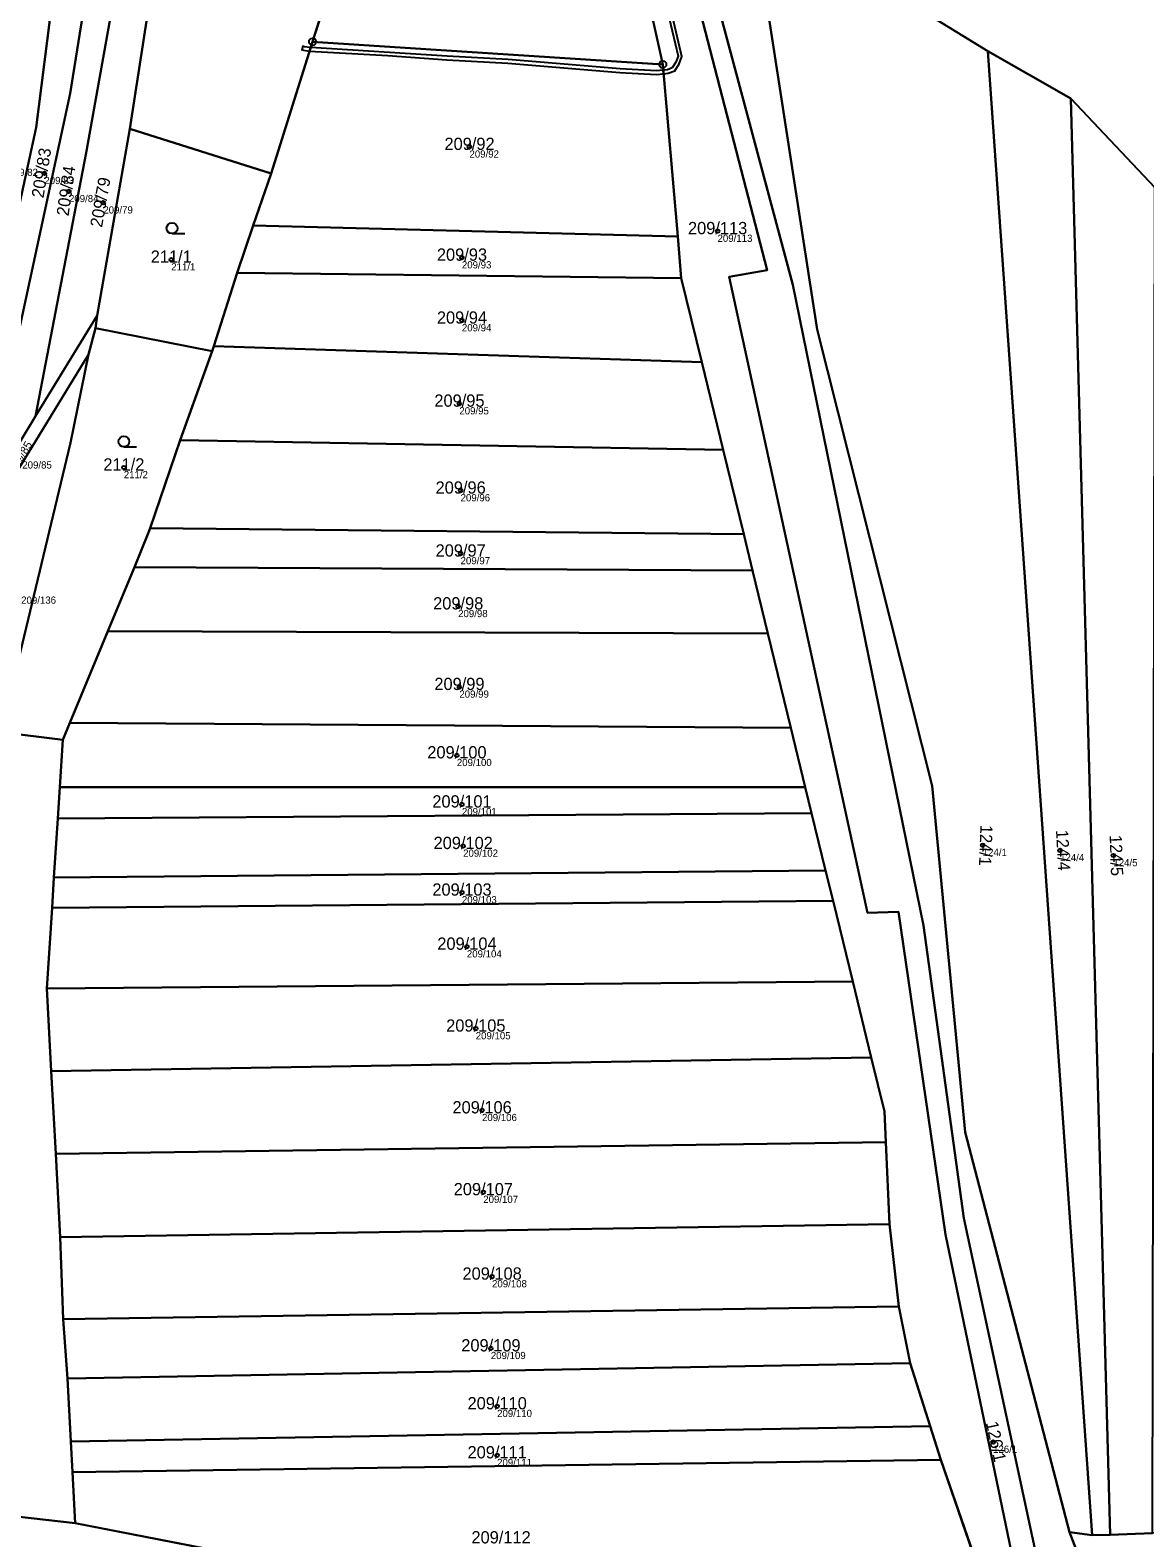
# Model space of a CAD drawing. Extents: x -603967 to -594699, y -1179315 to -1165625.
# Drawn here: x -597528.8 to -597374.2, y -1173008.8 to -1172799.8 of the extents above; entities that cross this region are included whole.
import ezdxf

# ---------------------------------------------------------------- set-up
doc = ezdxf.new("R2010")
doc.units = 0
for name, color, linetype in [('Definiční body', 7, 'Continuous'), ('Hranice parcel', 7, 'Continuous'), ('Parcelní čísla', 7, 'Continuous'), ('Polygon parcely', 7, 'Continuous'), ('Věcná břemena k části', 7, 'Continuous'), ('Značky bodu BP', 7, 'Continuous'), ('Značky kultur', 7, 'Continuous')]:
    doc.layers.add(name, color=color, linetype=linetype)

msp = doc.modelspace()

# ---------------------------------------------------------------- linework, layer by layer
at = {"layer": 'Definiční body'}
for centre in [(-597467.86, -1172815.98994), (-597526.79, -1172819.65994), (-597523.38, -1172822.15994), (-597518.62, -1172823.73994), (-597433.47, -1172827.66994), (-597468.91, -1172831.34994), (-597509.21, -1172831.62994), (-597468.91, -1172840.06994), (-597469.26, -1172851.58994), (-597515.78, -1172860.43994), (-597469.09, -1172863.63994), (-597469.09, -1172872.36994), (-597469.43, -1172879.69994), (-597469.26, -1172890.86994), (-597469.61, -1172900.34994), (-597468.91, -1172907.15994), (-597468.74, -1172912.91994), (-597396.7, -1172912.80994), (-597385.98, -1172913.52994), (-597378.59, -1172914.23994), (-597468.91, -1172919.37994), (-597468.22, -1172926.87994), (-597466.99, -1172938.22994), (-597466.12, -1172949.56994), (-597465.95, -1172960.91994), (-597464.73, -1172972.61994), (-597464.9, -1172982.56994), (-597464.03, -1172990.59994), (-597395.27, -1172995.56994), (-597464.03, -1172997.39994)]:
    msp.add_circle(centre, 0.25, dxfattribs=at)
at = {"layer": 'Hranice parcel'}
for p, q in [((-597440.1, -1172780.93), (-597426.6, -1172833.08)), ((-597484.17, -1172784.25), (-597489.6, -1172801.41)), ((-597445.39, -1172784.96), (-597441.07, -1172804.55)), ((-597395.98, -1172802.73), (-597418.94, -1172788.61)), ((-597489.6, -1172801.41), (-597495.37, -1172819.66)), ((-597441.07, -1172804.55), (-597489.6, -1172801.41)), ((-597384.49, -1172809.28), (-597395.98, -1172802.73)), ((-597381.55, -1173008.49), (-597395.98, -1172802.73)), ((-597438.99, -1172828.42), (-597441.07, -1172804.55)), ((-597379.03, -1173008.41), (-597384.49, -1172809.28)), ((-597372.84, -1172821.6), (-597384.49, -1172809.28)), ((-597519.47, -1172839.39), (-597514.93, -1172813.48)), ((-597514.93, -1172813.48), (-597495.37, -1172819.66)), ((-597495.37, -1172819.66), (-597497.83, -1172826.87)), ((-597497.83, -1172826.87), (-597500.07, -1172833.46)), ((-597497.83, -1172826.87), (-597438.99, -1172828.42)), ((-597438.49, -1172834.21), (-597438.99, -1172828.42)), ((-597500.07, -1172833.46), (-597503.32, -1172843.63)), ((-597500.07, -1172833.46), (-597438.49, -1172834.21)), ((-597435.65, -1172845.86), (-597438.49, -1172834.21)), ((-597528.03, -1172853.32), (-597519.47, -1172839.39)), ((-597519.7, -1172841.11), (-597519.47, -1172839.39)), ((-597520.68, -1172844.76), (-597519.7, -1172841.11)), ((-597503.54, -1172844.31), (-597519.7, -1172841.11)), ((-597503.32, -1172843.63), (-597503.54, -1172844.31)), ((-597503.32, -1172843.63), (-597435.65, -1172845.86)), ((-597530.61, -1172861.05), (-597520.68, -1172844.76)), ((-597503.54, -1172844.31), (-597507.98, -1172856.67)), ((-597432.7, -1172857.97), (-597435.65, -1172845.86)), ((-597536.07, -1172866.61), (-597528.03, -1172853.32)), ((-597507.98, -1172856.67), (-597512.13, -1172868.86)), ((-597507.98, -1172856.67), (-597432.7, -1172857.97)), ((-597429.84, -1172869.68), (-597432.7, -1172857.97)), ((-597512.13, -1172868.86), (-597429.84, -1172869.68)), ((-597428.61, -1172874.73), (-597429.84, -1172869.68)), ((-597514.32, -1172874.25), (-597518, -1172883.14)), ((-597514.32, -1172874.25), (-597428.61, -1172874.73)), ((-597426.48, -1172883.48), (-597428.61, -1172874.73)), ((-597518, -1172883.14), (-597523.27, -1172895.86)), ((-597518, -1172883.14), (-597426.48, -1172883.48)), ((-597423.3, -1172896.53), (-597426.48, -1172883.48)), ((-597523.27, -1172895.86), (-597524.24, -1172898.2)), ((-597523.27, -1172895.86), (-597423.3, -1172896.53)), ((-597524.24, -1172898.2), (-597532.79, -1172897.13)), ((-597524.24, -1172898.2), (-597524.66, -1172904.75)), ((-597421.3, -1172904.75), (-597423.3, -1172896.53)), ((-597524.66, -1172904.75), (-597524.94, -1172909.1)), ((-597524.66, -1172904.75), (-597421.3, -1172904.75)), ((-597420.42, -1172908.38), (-597421.3, -1172904.75)), ((-597524.94, -1172909.1), (-597420.42, -1172908.38)), ((-597418.48, -1172916.31), (-597420.42, -1172908.38)), ((-597524.94, -1172909.1), (-597525.46, -1172917.3)), ((-597525.46, -1172917.3), (-597418.48, -1172916.31)), ((-597417.46, -1172920.51), (-597418.48, -1172916.31)), ((-597525.46, -1172917.3), (-597525.73, -1172921.48)), ((-597525.73, -1172921.48), (-597417.46, -1172920.51)), ((-597414.73, -1172931.72), (-597417.46, -1172920.51)), ((-597525.73, -1172921.48), (-597526.44, -1172932.67)), ((-597526.44, -1172932.67), (-597414.73, -1172931.72)), ((-597526.44, -1172932.67), (-597525.83, -1172944.12)), ((-597412.16, -1172942.26), (-597414.73, -1172931.72)), ((-597525.83, -1172944.12), (-597412.16, -1172942.26)), ((-597525.83, -1172944.12), (-597525.22, -1172955.62)), ((-597525.22, -1172955.62), (-597410.15, -1172953.99)), ((-597409.65, -1172965.36), (-597410.15, -1172953.99)), ((-597525.22, -1172955.62), (-597524.61, -1172967.15)), ((-597524.61, -1172967.15), (-597409.65, -1172965.36)), ((-597524.61, -1172967.15), (-597524.21, -1172978.5)), ((-597408.34, -1172976.76), (-597409.65, -1172965.36)), ((-597524.21, -1172978.5), (-597408.34, -1172976.76)), ((-597406.76, -1172984.61), (-597408.34, -1172976.76)), ((-597524.21, -1172978.5), (-597523.57, -1172986.76)), ((-597523.57, -1172986.76), (-597406.76, -1172984.61)), ((-597403.99, -1172993.36), (-597406.76, -1172984.61)), ((-597523.57, -1172986.76), (-597523.11, -1172995.49)), ((-597523.11, -1172995.49), (-597403.99, -1172993.36)), ((-597402.51, -1172998.04), (-597403.99, -1172993.36)), ((-597523.11, -1172995.49), (-597522.89, -1172999.73)), ((-597522.89, -1172999.73), (-597402.51, -1172998.04)), ((-597396, -1173016.84), (-597402.51, -1172998.04)), ((-597522.89, -1172999.73), (-597522.51, -1173006.81)), ((-597522.51, -1173006.81), (-597435.74, -1173023.68)), ((-597384.66, -1173008.07), (-597366.96, -1173054.01)), ((-597384.66, -1173008.07), (-597381.55, -1173008.49)), ((-597381.55, -1173008.49), (-597379.03, -1173008.41)), ((-597379.03, -1173008.41), (-597373.16, -1173008.21))]:
    msp.add_line(p, q, dxfattribs=at)
for points in [[(-597537.99, -1172859.47), (-597527.91, -1172813.28), (-597523.41, -1172777.58)], [(-597534.46, -1172860.45), (-597523.22, -1172808.61), (-597518.36, -1172778.25)], [(-597514.19, -1172778.81), (-597520.99, -1172816.83), (-597528.03, -1172853.32)], [(-597514.93, -1172813.48), (-597511.25, -1172789.55), (-597509.62, -1172779.45)], [(-597341.88, -1173256.44), (-597340.26, -1173250.03), (-597339.32, -1173236.26), (-597344.17, -1173179.9), (-597353.54, -1173132.63), (-597361.17, -1173091.31), (-597366.08, -1173066.31), (-597374.64, -1173050.36), (-597380.37, -1173039.62), (-597387.47, -1173019.8), (-597399.32, -1172964.53), (-597404.92, -1172923.92), (-597423.04, -1172835.13), (-597437.05, -1172782.74)], [(-597424.67, -1172787.5), (-597427.53, -1172790.48), (-597419.68, -1172841.29), (-597403.71, -1172904.59), (-597399.15, -1172952.61), (-597384.66, -1173008.07)], [(-597426.6, -1172833.08), (-597431.85, -1172834.01), (-597412.69, -1172922.18), (-597408.39, -1172922.03), (-597401.86, -1172966.79), (-597391.47, -1173016.9), (-597386.2, -1173032.57)], [(-597532.79, -1172897.13), (-597523.17, -1172857.04), (-597520.68, -1172844.76)], [(-597512.13, -1172868.86), (-597512.34, -1172869.47), (-597514.32, -1172874.25)], [(-597410.15, -1172953.99), (-597410.34, -1172949.74), (-597412.16, -1172942.26)], [(-597522.51, -1173006.81), (-597530.67, -1173005.87), (-597534.65, -1173013.07)]]:
    msp.add_lwpolyline(points, dxfattribs=at)
at = {"layer": 'Polygon parcely'}
for points in [[(-597508.93, -1172775.18), (-597509.62, -1172779.45), (-597511.25, -1172789.55), (-597514.93, -1172813.48), (-597495.37, -1172819.66), (-597489.6, -1172801.41), (-597484.17, -1172784.25), (-597484.99, -1172777.4), (-597483.85, -1172750.31), (-597508.33, -1172749.24), (-597507.34, -1172765.31)], [(-597527.91, -1172813.28), (-597523.41, -1172777.58), (-597529.57, -1172776.75), (-597533.9, -1172807.29), (-597546.53, -1172872.69), (-597539.27, -1172859.11), (-597537.99, -1172859.47)], [(-597534.46, -1172860.45), (-597523.22, -1172808.61), (-597518.36, -1172778.25), (-597523.41, -1172777.58), (-597527.91, -1172813.28), (-597537.99, -1172859.47)], [(-597528.03, -1172853.32), (-597520.99, -1172816.83), (-597514.19, -1172778.81), (-597518.36, -1172778.25), (-597523.22, -1172808.61), (-597534.46, -1172860.45), (-597536.07, -1172866.61)], [(-597509.62, -1172779.45), (-597514.19, -1172778.81), (-597520.99, -1172816.83), (-597528.03, -1172853.32), (-597519.47, -1172839.39), (-597514.93, -1172813.48), (-597511.25, -1172789.55)], [(-597445.39, -1172784.96), (-597483.57, -1172782.35), (-597484.17, -1172784.25), (-597489.6, -1172801.41), (-597441.07, -1172804.55)], [(-597419.68, -1172841.29), (-597403.71, -1172904.59), (-597399.15, -1172952.61), (-597384.66, -1173008.07), (-597381.55, -1173008.49), (-597395.98, -1172802.73), (-597418.94, -1172788.61), (-597424.67, -1172787.5), (-597427.53, -1172790.48)], [(-597495.37, -1172819.66), (-597497.83, -1172826.87), (-597438.99, -1172828.42), (-597441.07, -1172804.55), (-597489.6, -1172801.41)], [(-597379.03, -1173008.41), (-597384.49, -1172809.28), (-597395.98, -1172802.73), (-597381.55, -1173008.49)], [(-597384.49, -1172809.28), (-597379.03, -1173008.41), (-597373.16, -1173008.21), (-597372.84, -1172821.6)], [(-597514.93, -1172813.48), (-597519.47, -1172839.39), (-597519.7, -1172841.11), (-597503.54, -1172844.31), (-597503.32, -1172843.63), (-597500.07, -1172833.46), (-597497.83, -1172826.87), (-597495.37, -1172819.66)], [(-597500.07, -1172833.46), (-597438.49, -1172834.21), (-597438.99, -1172828.42), (-597497.83, -1172826.87)], [(-597435.65, -1172845.86), (-597438.49, -1172834.21), (-597500.07, -1172833.46), (-597503.32, -1172843.63)], [(-597520.68, -1172844.76), (-597519.7, -1172841.11), (-597519.47, -1172839.39), (-597528.03, -1172853.32), (-597536.07, -1172866.61), (-597537.63, -1172872.57), (-597530.61, -1172861.05)], [(-597503.54, -1172844.31), (-597519.7, -1172841.11), (-597520.68, -1172844.76), (-597523.17, -1172857.04), (-597532.79, -1172897.13), (-597524.24, -1172898.2), (-597523.27, -1172895.86), (-597518, -1172883.14), (-597514.32, -1172874.25), (-597512.34, -1172869.47), (-597512.13, -1172868.86), (-597507.98, -1172856.67)], [(-597503.32, -1172843.63), (-597503.54, -1172844.31), (-597507.98, -1172856.67), (-597432.7, -1172857.97), (-597435.65, -1172845.86)], [(-597523.17, -1172857.04), (-597520.68, -1172844.76), (-597530.61, -1172861.05), (-597537.43, -1172897.02), (-597532.79, -1172897.13)], [(-597507.98, -1172856.67), (-597512.13, -1172868.86), (-597429.84, -1172869.68), (-597432.7, -1172857.97)], [(-597512.13, -1172868.86), (-597512.34, -1172869.47), (-597514.32, -1172874.25), (-597428.61, -1172874.73), (-597429.84, -1172869.68)], [(-597514.32, -1172874.25), (-597518, -1172883.14), (-597426.48, -1172883.48), (-597428.61, -1172874.73)], [(-597518, -1172883.14), (-597523.27, -1172895.86), (-597423.3, -1172896.53), (-597426.48, -1172883.48)], [(-597523.27, -1172895.86), (-597524.24, -1172898.2), (-597524.66, -1172904.75), (-597421.3, -1172904.75), (-597423.3, -1172896.53)], [(-597524.94, -1172909.1), (-597420.42, -1172908.38), (-597421.3, -1172904.75), (-597524.66, -1172904.75)], [(-597418.48, -1172916.31), (-597420.42, -1172908.38), (-597524.94, -1172909.1), (-597525.46, -1172917.3)], [(-597417.46, -1172920.51), (-597418.48, -1172916.31), (-597525.46, -1172917.3), (-597525.73, -1172921.48)], [(-597414.73, -1172931.72), (-597417.46, -1172920.51), (-597525.73, -1172921.48), (-597526.44, -1172932.67)], [(-597525.83, -1172944.12), (-597412.16, -1172942.26), (-597414.73, -1172931.72), (-597526.44, -1172932.67)], [(-597525.22, -1172955.62), (-597410.15, -1172953.99), (-597410.34, -1172949.74), (-597412.16, -1172942.26), (-597525.83, -1172944.12)], [(-597409.65, -1172965.36), (-597410.15, -1172953.99), (-597525.22, -1172955.62), (-597524.61, -1172967.15)], [(-597408.34, -1172976.76), (-597409.65, -1172965.36), (-597524.61, -1172967.15), (-597524.21, -1172978.5)], [(-597406.76, -1172984.61), (-597408.34, -1172976.76), (-597524.21, -1172978.5), (-597523.57, -1172986.76)], [(-597403.99, -1172993.36), (-597406.76, -1172984.61), (-597523.57, -1172986.76), (-597523.11, -1172995.49)], [(-597522.89, -1172999.73), (-597402.51, -1172998.04), (-597403.99, -1172993.36), (-597523.11, -1172995.49)], [(-597435.74, -1173023.68), (-597396, -1173016.84), (-597402.51, -1172998.04), (-597522.89, -1172999.73), (-597522.51, -1173006.81)], [(-597366.96, -1173054.01), (-597253.51, -1173043.9), (-597244.24, -1173003.81), (-597264.88, -1173004.51), (-597272.44, -1173004.77), (-597277.95, -1173004.96), (-597285.49, -1173005.27), (-597306.63, -1173005.94), (-597314.04, -1173005.91), (-597325.15, -1173006.26), (-597341.63, -1173006.91), (-597357.18, -1173007.66), (-597367.66, -1173008.02), (-597373.16, -1173008.21), (-597379.03, -1173008.41), (-597381.55, -1173008.49), (-597384.66, -1173008.07)], [(-597530.67, -1173005.87), (-597534.65, -1173013.07), (-597530.12, -1173013.68), (-597440.1, -1173025.7), (-597438.19, -1173025.94), (-597435.74, -1173023.68), (-597522.51, -1173006.81)]]:
    msp.add_lwpolyline(points, close=True, dxfattribs=at)
for points in [[(-597387.47, -1173019.8), (-597399.32, -1172964.53), (-597404.92, -1172923.92), (-597423.04, -1172835.13), (-597437.05, -1172782.74), (-597440.1, -1172780.93), (-597426.6, -1172833.08), (-597431.85, -1172834.01), (-597412.69, -1172922.18), (-597408.39, -1172922.03), (-597401.86, -1172966.79), (-597391.47, -1173016.9)], [(-597391.47, -1173016.9), (-597401.86, -1172966.79), (-597408.39, -1172922.03), (-597412.69, -1172922.18), (-597431.85, -1172834.01), (-597426.6, -1172833.08), (-597440.1, -1172780.93)], [(-597366.96, -1173054.01), (-597384.66, -1173008.07), (-597399.15, -1172952.61), (-597403.71, -1172904.59), (-597419.68, -1172841.29), (-597427.53, -1172790.48), (-597424.67, -1172787.5), (-597430.29, -1172786.38), (-597437.05, -1172782.74), (-597423.04, -1172835.13), (-597404.92, -1172923.92), (-597399.32, -1172964.53), (-597387.47, -1173019.8)], [(-597445.39, -1172784.96), (-597441.07, -1172804.55), (-597438.99, -1172828.42), (-597438.49, -1172834.21), (-597435.65, -1172845.86), (-597432.7, -1172857.97), (-597429.84, -1172869.68), (-597428.61, -1172874.73), (-597426.48, -1172883.48), (-597423.3, -1172896.53), (-597421.3, -1172904.75), (-597420.42, -1172908.38), (-597418.48, -1172916.31), (-597417.46, -1172920.51), (-597414.73, -1172931.72), (-597412.16, -1172942.26), (-597410.34, -1172949.74), (-597410.15, -1172953.99), (-597409.65, -1172965.36), (-597408.34, -1172976.76), (-597406.76, -1172984.61), (-597403.99, -1172993.36), (-597402.51, -1172998.04), (-597396, -1173016.84)], [(-597208.24, -1172829.67), (-597328.95, -1172806.15), (-597418.94, -1172788.61), (-597395.98, -1172802.73), (-597384.49, -1172809.28), (-597372.84, -1172821.6), (-597365.79, -1172823.44), (-597353.45, -1172828.38), (-597333.31, -1172831.9), (-597315.56, -1172835.54), (-597302.01, -1172837.44), (-597294.35, -1172837.92), (-597274.62, -1172842.36)], [(-597530.67, -1173005.87), (-597522.51, -1173006.81), (-597522.89, -1172999.73), (-597523.11, -1172995.49), (-597523.57, -1172986.76), (-597524.21, -1172978.5), (-597524.61, -1172967.15), (-597525.22, -1172955.62), (-597525.83, -1172944.12), (-597526.44, -1172932.67), (-597525.73, -1172921.48), (-597525.46, -1172917.3), (-597524.94, -1172909.1), (-597524.66, -1172904.75), (-597524.24, -1172898.2), (-597532.79, -1172897.13)]]:
    msp.add_lwpolyline(points, dxfattribs=at)
at = {"layer": 'Věcná břemena k části'}
for points in [[(-597441, -1172805.35), (-597440.96, -1172805.85), (-597440.3, -1172805.77), (-597439.41, -1172805.43), (-597438.81, -1172804.47), (-597438.42, -1172803.45), (-597440.52, -1172794.48), (-597441.71, -1172789.84), (-597441.84, -1172788.25), (-597441.44, -1172787.54), (-597441.77, -1172786.7), (-597442.23, -1172786.88), (-597442, -1172787.5), (-597442.36, -1172788.13), (-597442.21, -1172789.92), (-597441, -1172794.6), (-597438.94, -1172803.41), (-597439.25, -1172804.25), (-597439.75, -1172805.03), (-597440.42, -1172805.29)], [(-597490.02, -1172802.72), (-597489.86, -1172802.23), (-597490.04, -1172802.22), (-597490.75, -1172802.11), (-597490.98, -1172802.04), (-597491.11, -1172802.53), (-597490.86, -1172802.59)], [(-597489.86, -1172802.23), (-597490.02, -1172802.72), (-597479.18, -1172803.32), (-597471, -1172803.93), (-597462.52, -1172804.39), (-597447, -1172805.68), (-597441.91, -1172805.96), (-597440.96, -1172805.85), (-597441, -1172805.35), (-597441.93, -1172805.46), (-597446.96, -1172805.18), (-597462.48, -1172803.89), (-597470.96, -1172803.43)]]:
    msp.add_lwpolyline(points, close=True, dxfattribs=at)
at = {"layer": 'Značky bodu BP'}
for centre, radius in [((-597489.6, -1172801.40988), 0.5), ((-597489.6, -1172801.40988), 0.0303), ((-597441.07, -1172804.54988), 0.5), ((-597441.07, -1172804.54988), 0.0303)]:
    msp.add_circle(centre, radius, dxfattribs=at)
at = {"layer": 'Značky kultur'}
for p, q in [((-597509.093, -1172828.02), (-597507.343, -1172828.02)), ((-597515.773, -1172857.59), (-597514.023, -1172857.59))]:
    msp.add_line(p, q, dxfattribs=at)
for centre in [(-597509.09286, -1172827.26981), (-597515.77286, -1172856.83981)]:
    msp.add_circle(centre, 0.75, dxfattribs=at)

# ---------------------------------------------------------------- texts
at = {"layer": 'Definiční body'}
for s, p in [('209/92', (-597467.86, -1172817.479)), ('209/82', (-597531.77, -1172820.019)), ('209/83', (-597526.79, -1172821.149)), ('209/84', (-597523.38, -1172823.649)), ('209/79', (-597518.62, -1172825.229)), ('209/113', (-597433.47, -1172829.159)), ('211/1', (-597509.21, -1172833.119)), ('209/93', (-597468.91, -1172832.839)), ('209/94', (-597468.91, -1172841.559)), ('209/95', (-597469.26, -1172853.079)), ('209/85', (-597529.85, -1172860.589)), ('211/2', (-597515.78, -1172861.929)), ('209/96', (-597469.09, -1172865.129)), ('209/97', (-597469.09, -1172873.859)), ('209/136', (-597530.01, -1172879.329)), ('209/98', (-597469.43, -1172881.189)), ('209/99', (-597469.26, -1172892.359)), ('209/100', (-597469.61, -1172901.839)), ('209/101', (-597468.91, -1172908.649)), ('209/102', (-597468.74, -1172914.409)), ('124/1', (-597396.7, -1172914.299)), ('124/4', (-597385.98, -1172915.019)), ('124/5', (-597378.59, -1172915.729)), ('209/103', (-597468.91, -1172920.869)), ('209/104', (-597468.22, -1172928.369)), ('209/105', (-597466.99, -1172939.719)), ('209/106', (-597466.12, -1172951.059)), ('209/107', (-597465.95, -1172962.409)), ('209/108', (-597464.73, -1172974.109)), ('209/109', (-597464.9, -1172984.059)), ('209/110', (-597464.03, -1172992.089)), ('126/1', (-597395.27, -1172997.059)), ('209/111', (-597464.03, -1172998.889))]:
    msp.add_text(s, height=0.999996, dxfattribs=at).set_placement(p)
at = {"layer": 'Parcelní čísla'}
for s, p in [('209/92', (-597471.326, -1172816.415)), ('209/113', (-597437.566, -1172828.095)), ('211/1', (-597512.046, -1172832.055)), ('209/93', (-597472.376, -1172831.775)), ('209/94', (-597472.376, -1172840.495)), ('209/95', (-597472.726, -1172852.015)), ('211/2', (-597518.616, -1172860.865)), ('209/96', (-597472.556, -1172864.065)), ('209/97', (-597472.556, -1172872.795)), ('209/98', (-597472.896, -1172880.125)), ('209/99', (-597472.726, -1172891.295)), ('209/100', (-597473.706, -1172900.775)), ('209/101', (-597473.006, -1172907.585)), ('209/102', (-597472.836, -1172913.345)), ('209/103', (-597473.006, -1172919.805)), ('209/104', (-597472.316, -1172927.305)), ('209/105', (-597471.086, -1172938.655)), ('209/106', (-597470.216, -1172949.995)), ('209/107', (-597470.046, -1172961.345)), ('209/108', (-597468.826, -1172973.045)), ('209/109', (-597468.996, -1172982.995)), ('209/110', (-597468.126, -1172991.025)), ('209/111', (-597468.126, -1172997.825)), ('209/112', (-597467.586, -1173009.615))]:
    msp.add_text(s, height=1.699998, dxfattribs=at).set_placement(p)
for s, height, rotation, p in [('209/83', 1.699998, 81, (-597526.912, -1172823.15)), ('209/84', 1.699998, 82, (-597523.441, -1172825.651)), ('209/79', 1.699998, 80, (-597518.803, -1172827.227)), ('209/85', 1.14, 59, (-597530.802, -1172861.239)), ('124/1', 1.699998, 267.9999972, (-597397.025, -1172909.96)), ('124/4', 1.699998, 273, (-597386.552, -1172910.72)), ('124/5', 1.699998, 272, (-597379.113, -1172911.42)), ('126/1', 1.699998, 282, (-597396.275, -1172992.884))]:
    msp.add_text(s, height=height, rotation=rotation, dxfattribs=at).set_placement(p)

doc.saveas('drawing.dxf')
